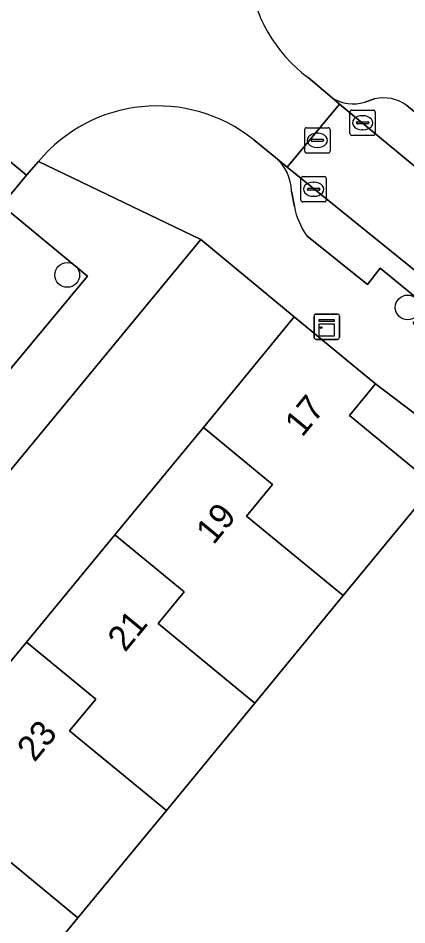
# Model space of a CAD drawing. Extents: x 162073 to 163043, y 381818 to 382561.
# Drawn here: x 162602.84 to 162618.19, y 382089.07 to 382124.92 of the extents above; entities that cross this region are included whole.
import ezdxf

# ---------------------------------------------------------------- set-up
doc = ezdxf.new("R2010")
doc.units = 0
for name, color, linetype in [('IMGEO_Boom', 7, 'Continuous'), ('IMGEO_Erf', 7, 'Continuous'), ('IMGEO_Groenvoorziening', 7, 'Continuous'), ('IMGEO_Kast', 7, 'Continuous'), ('IMGEO_Kolk', 7, 'Continuous'), ('IMGEO_Pand', 7, 'Continuous'), ('IMGEO_Pand_nummerreeks', 7, 'Continuous'), ('IMGEO_Parkeervlak_open', 7, 'Continuous'), ('IMGEO_Rijbaan_lokaal_open', 7, 'Continuous'), ('IMGEO_Rioolput', 7, 'Continuous'), ('IMGEO_Voetpad_open', 7, 'Continuous')]:
    doc.layers.add(name, color=color, linetype=linetype)

msp = doc.modelspace()

# ---------------------------------------------------------------- linework, layer by layer
at = {"layer": 'IMGEO_Boom'}
for centre in [(162604.776, 382114.768), (162618.226, 382113.485)]:
    msp.add_circle(centre, 0.489, dxfattribs=at)
at = {"layer": 'IMGEO_Erf'}
for points in [[(162575.851, 382068.806), (162577.972, 382071.383), (162578.824, 382070.682), (162582.19, 382074.771), (162585.685, 382079.017), (162589.181, 382083.264), (162592.676, 382087.51), (162596.172, 382091.756), (162599.667, 382096.002), (162603.163, 382100.249), (162606.658, 382104.495), (162610.154, 382108.742), (162613.747, 382113.107), (162610.06, 382116.173), (162569.158, 382066.59)], [(162662.101, 382069.449), (162657.097, 382075.079), (162644.151, 382088.188), (162639.153, 382092.704), (162629.902, 382100.628), (162628.401, 382099.157), (162626.282, 382100.754), (162622.257, 382095.863), (162619.893, 382097.809), (162623.918, 382102.7), (162624.445, 382103.361), (162622.003, 382105.405), (162622.12, 382105.524), (162619.972, 382107.263), (162619.275, 382106.453), (162615.684, 382102.091), (162612.189, 382097.844), (162608.693, 382093.598), (162605.197, 382089.352), (162601.702, 382085.105), (162598.207, 382080.859), (162594.712, 382076.613), (162591.216, 382072.366), (162587.721, 382068.121)]]:
    msp.add_lwpolyline(points, dxfattribs=at)
at = {"layer": 'IMGEO_Groenvoorziening'}
msp.add_lwpolyline([(162593.727, 382100.46), (162605.577, 382114.723), (162602.523, 382117.255), (162590.713, 382103.042)], close=True, dxfattribs=at)
at = {"layer": 'IMGEO_Kast'}
for p, q in [((162614.528, 382112.296), (162614.528, 382113.137)), ((162614.528, 382113.137), (162614.528, 382112.296)), ((162614.603, 382113.221), (162615.444, 382113.221)), ((162615.444, 382113.221), (162614.603, 382113.221)), ((162615.528, 382113.146), (162615.528, 382112.305)), ((162615.528, 382112.305), (162615.528, 382113.146)), ((162615.453, 382112.221), (162614.612, 382112.221)), ((162614.612, 382112.221), (162615.453, 382112.221))]:
    msp.add_line(p, q, dxfattribs=at)
for points in [[(162614.723, 382113.011), (162615.323, 382113.011), (162615.323, 382112.926), (162614.723, 382112.926), (162614.723, 382113.011)], [(162614.723, 382112.836), (162615.323, 382112.836), (162615.323, 382112.347), (162614.723, 382112.347), (162614.723, 382112.836)]]:
    msp.add_lwpolyline(points, dxfattribs=at)
msp.add_circle((162614.807, 382112.685), 0.0377, dxfattribs=at)
for centre, start, end in [((162614.606, 382113.143), 92.4484, 184.2845), ((162614.606, 382113.143), 92.4484, 184.2845), ((162615.45, 382113.143), 2.4484, 94.2845), ((162615.45, 382113.143), 2.4484, 94.2845), ((162614.606, 382112.299), 182.4484, 274.2845), ((162614.606, 382112.299), 182.4484, 274.2845), ((162615.45, 382112.299), 272.4484, 4.2845), ((162615.45, 382112.299), 272.4484, 4.2845)]:
    msp.add_arc(centre, 0.0779, start, end, dxfattribs=at)
at = {"layer": 'IMGEO_Kolk'}
for p, q in [((162615.943, 382120.357), (162615.943, 382121.209)), ((162616.018, 382121.283), (162616.87, 382121.283)), ((162616.944, 382121.209), (162616.944, 382120.357)), ((162616.431, 382121.063), (162616.456, 382121.063)), ((162616.202, 382120.777), (162616.202, 382120.789)), ((162616.64, 382120.74), (162616.242, 382120.74)), ((162616.245, 382120.826), (162616.643, 382120.826)), ((162616.454, 382120.503), (162616.429, 382120.503)), ((162616.686, 382120.789), (162616.686, 382120.777)), ((162616.87, 382120.283), (162616.018, 382120.283)), ((162614.01, 382117.731), (162614.01, 382118.583)), ((162614.085, 382118.657), (162614.937, 382118.657)), ((162614.498, 382118.437), (162614.523, 382118.437)), ((162615.011, 382118.583), (162615.011, 382117.731)), ((162614.269, 382118.151), (162614.269, 382118.163)), ((162614.707, 382118.114), (162614.309, 382118.114)), ((162614.312, 382118.2), (162614.71, 382118.2)), ((162614.753, 382118.163), (162614.753, 382118.151)), ((162614.937, 382117.657), (162614.085, 382117.657)), ((162614.521, 382117.877), (162614.496, 382117.877))]:
    msp.add_line(p, q, dxfattribs=at)
for points in [[(162615.943, 382120.357), (162615.943, 382121.209)], [(162616.018, 382121.283), (162616.87, 382121.283)], [(162616.944, 382121.209), (162616.944, 382120.357)], [(162616.87, 382120.283), (162616.018, 382120.283)], [(162614.01, 382117.731), (162614.01, 382118.583)], [(162614.085, 382118.657), (162614.937, 382118.657)], [(162615.011, 382118.583), (162615.011, 382117.731)], [(162614.937, 382117.657), (162614.085, 382117.657)]]:
    msp.add_lwpolyline(points, dxfattribs=at)
for centre, radius, start, end in [((162616.02, 382121.207), 0.0765, 91.552, 178.448), ((162616.02, 382121.207), 0.0765, 91.552, 178.448), ((162616.868, 382121.207), 0.0765, 1.552, 88.448), ((162616.868, 382121.207), 0.0765, 1.552, 88.448), ((162616.242, 382120.786), 0.0403, 85.8775, 175.7526), ((162616.239, 382120.776), 0.0366, 178.938, 274.7102), ((162616.643, 382120.783), 0.043, 264.8664, 352.4533), ((162616.647, 382120.788), 0.0386, 1.7309, 96.639), ((162616.02, 382120.359), 0.0765, 181.552, 268.448), ((162616.02, 382120.359), 0.0765, 181.552, 268.448), ((162616.868, 382120.359), 0.0765, 271.552, 358.448), ((162616.868, 382120.359), 0.0765, 271.552, 358.448), ((162614.087, 382118.581), 0.0765, 91.552, 178.448), ((162614.087, 382118.581), 0.0765, 91.552, 178.448), ((162614.935, 382118.581), 0.0765, 1.552, 88.448), ((162614.935, 382118.581), 0.0765, 1.552, 88.448), ((162614.309, 382118.16), 0.0403, 85.8775, 175.7526), ((162614.306, 382118.15), 0.0366, 178.938, 274.7102), ((162614.71, 382118.157), 0.043, 264.8664, 352.4533), ((162614.714, 382118.162), 0.0386, 1.7309, 96.639), ((162614.087, 382117.733), 0.0765, 181.552, 268.448), ((162614.087, 382117.733), 0.0765, 181.552, 268.448), ((162614.935, 382117.733), 0.0765, 271.552, 358.448), ((162614.935, 382117.733), 0.0765, 271.552, 358.448)]:
    msp.add_arc(centre, radius, start, end, dxfattribs=at)
for centre, major_axis, ratio, start_param, end_param in [((162616.43, 382120.783), (-0.387, 0.002), 0.722429, 4.712389, 7.853982), ((162616.455, 382120.783), (-0.39, 0.002), 0.717154, 1.570796, 4.712389), ((162614.497, 382118.157), (-0.387, 0.002), 0.722429, 4.712389, 7.853982), ((162614.522, 382118.157), (-0.39, 0.002), 0.717154, 1.570796, 4.712389)]:
    msp.add_ellipse(centre, major_axis=major_axis, ratio=ratio, start_param=start_param, end_param=end_param, dxfattribs=at)
at = {"layer": 'IMGEO_Pand'}
for points in [[(162610.154, 382108.742), (162612.891, 382106.488), (162611.862, 382105.238), (162615.684, 382102.091), (162619.275, 382106.453), (162615.927, 382109.209), (162616.959, 382110.463), (162613.747, 382113.107)], [(162606.658, 382104.495), (162609.396, 382102.242), (162608.366, 382100.992), (162612.189, 382097.844), (162615.684, 382102.091), (162611.862, 382105.238), (162612.891, 382106.488), (162610.154, 382108.742)], [(162606.658, 382104.495), (162603.163, 382100.249), (162605.901, 382097.996), (162604.871, 382096.745), (162608.693, 382093.598), (162612.189, 382097.844), (162608.366, 382100.992), (162609.396, 382102.242)], [(162605.197, 382089.352), (162608.693, 382093.598), (162604.871, 382096.745), (162605.901, 382097.996), (162603.163, 382100.249), (162599.667, 382096.002), (162602.405, 382093.749), (162601.376, 382092.498)], [(162596.172, 382091.756), (162598.91, 382089.503), (162597.88, 382088.252), (162601.702, 382085.105), (162605.197, 382089.352), (162601.376, 382092.498), (162602.405, 382093.749), (162599.667, 382096.002)]]:
    msp.add_lwpolyline(points, close=True, dxfattribs=at)
at = {"layer": 'IMGEO_Parkeervlak_open'}
for points in [[(162615.241, 382121.774), (162615.533, 382121.526), (162619.229, 382118.462), (162623, 382115.365), (162628.436, 382110.86)], [(162616.913, 382121.728), (162616.531, 382121.602)], [(162627.385, 382113.902), (162622.549, 382117.941), (162622.09, 382117.346), (162620.128, 382118.913), (162620.662, 382119.432), (162618.194, 382121.47)], [(162613.47, 382119.034), (162613.003, 382119.413)], [(162624.187, 382110.211), (162626.645, 382108.247), (162622.149, 382111.974), (162618.203, 382115.191), (162613.47, 382119.034)], [(162613.639, 382118.082), (162613.751, 382117.472)], [(162614.242, 382116.315), (162616.635, 382114.391), (162617.145, 382115.037), (162618.955, 382113.547), (162618.445, 382112.863), (162620.788, 382110.976), (162621.419, 382110.478), (162621.788, 382110.469), (162622.856, 382110.582)]]:
    msp.add_lwpolyline(points, dxfattribs=at)
for centre, radius, start, end in [((162616.063, 382123.019), 1.492, 236.553, 288.2577), ((162617.273, 382120.204), 1.565, 53.9431, 103.2822), ((162611.798, 382118.02), 1.842, 1.94, 49.1404), ((162616.592, 382117.995), 2.888, 190.428, 215.5621)]:
    msp.add_arc(centre, radius, start, end, dxfattribs=at)
at = {"layer": 'IMGEO_Rijbaan_lokaal_open'}
for points in [[(162599.157, 382123.241), (162598.581, 382122.503), (162603.172, 382118.715), (162603.635, 382119.248)], [(162612.143, 382120.111), (162613.003, 382119.413), (162613.47, 382119.034), (162615.533, 382121.526), (162615.241, 382121.774), (162614.29, 382122.578)], [(162645.88, 382095.919), (162643.616, 382097.962), (162640.492, 382100.753), (162637.528, 382103.355), (162633.363, 382106.764), (162632.463, 382107.512), (162632.258, 382107.683), (162629.323, 382110.123), (162628.436, 382110.86), (162623, 382115.365), (162619.229, 382118.462), (162615.533, 382121.526), (162613.47, 382119.034), (162618.203, 382115.191), (162622.149, 382111.974), (162626.645, 382108.247), (162627.428, 382107.618), (162630.399, 382105.231), (162630.556, 382105.1), (162635.285, 382101.121), (162638.389, 382098.519), (162641.364, 382095.768), (162644.268, 382093.096), (162648.402, 382089.208)]]:
    msp.add_lwpolyline(points, dxfattribs=at)
msp.add_lwpolyline([(162591.337, 382104.582), (162600.415, 382115.377), (162602.191, 382117.527), (162603.172, 382118.715), (162598.581, 382122.503), (162595.822, 382119.179), (162590.217, 382112.567), (162584.034, 382104.954), (162578.776, 382098.764), (162571.06, 382089.409), (162560.737, 382076.887), (162562.746, 382075.204), (162565.272, 382073.089), (162565.762, 382073.683), (162567.453, 382075.734), (162575.266, 382085.291), (162582.805, 382094.226)], close=True, dxfattribs=at)
for centre, radius, start, end in [((162617.801, 382127.301), 5.885, 139.6907, 233.3773), ((162608.328, 382115.355), 6.097, 51.2647, 140.3191)]:
    msp.add_arc(centre, radius, start, end, dxfattribs=at)
at = {"layer": 'IMGEO_Rioolput'}
for p, q in [((162614.159, 382119.662), (162614.159, 382120.514)), ((162614.234, 382120.588), (162615.086, 382120.588)), ((162615.16, 382120.514), (162615.16, 382119.662)), ((162614.461, 382120.131), (162614.859, 382120.131)), ((162614.647, 382120.368), (162614.672, 382120.368)), ((162614.418, 382120.082), (162614.418, 382120.094)), ((162614.856, 382120.045), (162614.458, 382120.045)), ((162614.67, 382119.808), (162614.645, 382119.808)), ((162614.902, 382120.094), (162614.902, 382120.082)), ((162615.086, 382119.588), (162614.234, 382119.588))]:
    msp.add_line(p, q, dxfattribs=at)
for points in [[(162614.159, 382119.662), (162614.159, 382120.514)], [(162614.234, 382120.588), (162615.086, 382120.588)], [(162615.16, 382120.514), (162615.16, 382119.662)], [(162615.086, 382119.588), (162614.234, 382119.588)]]:
    msp.add_lwpolyline(points, dxfattribs=at)
for centre, radius, start, end in [((162614.236, 382120.512), 0.0765, 91.552, 178.448), ((162614.236, 382120.512), 0.0765, 91.552, 178.448), ((162615.084, 382120.512), 0.0765, 1.552, 88.448), ((162615.084, 382120.512), 0.0765, 1.552, 88.448), ((162614.458, 382120.091), 0.0403, 85.8775, 175.7526), ((162614.863, 382120.093), 0.0386, 1.7309, 96.639), ((162614.455, 382120.081), 0.0366, 178.938, 274.7102), ((162614.859, 382120.088), 0.043, 264.8664, 352.4533), ((162614.236, 382119.664), 0.0765, 181.552, 268.448), ((162614.236, 382119.664), 0.0765, 181.552, 268.448), ((162615.084, 382119.664), 0.0765, 271.552, 358.448), ((162615.084, 382119.664), 0.0765, 271.552, 358.448)]:
    msp.add_arc(centre, radius, start, end, dxfattribs=at)
for centre, major_axis, ratio, start_param, end_param in [((162614.646, 382120.088), (-0.387, 0.002), 0.722429, 4.712389, 7.853982), ((162614.671, 382120.088), (-0.39, 0.002), 0.717154, 1.570796, 4.712389)]:
    msp.add_ellipse(centre, major_axis=major_axis, ratio=ratio, start_param=start_param, end_param=end_param, dxfattribs=at)
at = {"layer": 'IMGEO_Voetpad_open'}
for points in [[(162614.29, 382122.578), (162615.241, 382121.774)], [(162616.531, 382121.602), (162616.913, 382121.728)], [(162618.194, 382121.47), (162620.662, 382119.432), (162620.128, 382118.913), (162622.09, 382117.346), (162622.549, 382117.941), (162627.385, 382113.902)], [(162613.003, 382119.413), (162612.143, 382120.111)], [(162603.635, 382119.248), (162610.06, 382116.173), (162613.747, 382113.107), (162616.959, 382110.463), (162629.902, 382100.628), (162639.153, 382092.704), (162644.151, 382088.188), (162657.097, 382075.079), (162662.101, 382069.449), (162697.896, 382025.512), (162697.016, 382024.713), (162709.893, 382008.991), (162713.526, 382011.966), (162713.195, 382012.363)], [(162613.751, 382117.472), (162613.639, 382118.082)], [(162622.856, 382110.582), (162621.788, 382110.469), (162621.419, 382110.478), (162620.788, 382110.976), (162618.445, 382112.863), (162618.955, 382113.547), (162617.145, 382115.037), (162616.635, 382114.391), (162614.242, 382116.315)]]:
    msp.add_lwpolyline(points, dxfattribs=at)
for points in [[(162610.06, 382116.173), (162603.635, 382119.248), (162603.172, 382118.715), (162602.191, 382117.527), (162602.523, 382117.255), (162605.577, 382114.723), (162593.727, 382100.46), (162592.91, 382099.538), (162581.728, 382085.956), (162581.041, 382085.025), (162569.225, 382070.759), (162566.191, 382073.321), (162565.762, 382073.683), (162565.272, 382073.089), (162564.01, 382070.969), (162569.158, 382066.59)], [(162616.959, 382110.463), (162615.927, 382109.209), (162619.275, 382106.453), (162619.972, 382107.263), (162622.12, 382105.524), (162622.003, 382105.405), (162624.445, 382103.361), (162623.918, 382102.7), (162626.282, 382100.754), (162628.401, 382099.157), (162629.902, 382100.628)]]:
    msp.add_lwpolyline(points, close=True, dxfattribs=at)
for centre, radius, start, end in [((162617.801, 382127.301), 5.885, 139.6907, 233.3773), ((162616.063, 382123.019), 1.492, 236.553, 288.2577), ((162617.273, 382120.204), 1.565, 53.9431, 103.2822), ((162608.328, 382115.355), 6.097, 51.2647, 140.3191), ((162611.798, 382118.02), 1.842, 1.94, 49.1404), ((162616.592, 382117.995), 2.888, 190.428, 215.5621)]:
    msp.add_arc(centre, radius, start, end, dxfattribs=at)

# ---------------------------------------------------------------- texts
at = {"layer": 'IMGEO_Pand_nummerreeks'}
for s, p in [('17', (162614.059, 382108.325)), ('19', (162610.552, 382104.066)), ('21', (162607.06, 382099.823)), ('23', (162603.482, 382095.476))]:
    msp.add_text(s, height=1, rotation=50.5398, dxfattribs=at).set_placement(p)

doc.saveas('drawing.dxf')
